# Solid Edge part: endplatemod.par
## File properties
Author: Deepak Maini
Template: NORMENG.PAR
Last saved by: CADCIM
Revision: 3
Application: Solid Edge
Accuracy: 0.99
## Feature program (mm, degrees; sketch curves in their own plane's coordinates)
sketch for "unnamed Protrusion 1" plane through (0, 0, 0) normal (0, 0, 1) x-axis (1, 0, 0)
  line (-50.8, 46.0858) -> (-50.8, -55.5142)
  line (-50.8, -55.5142) -> (50.8, -55.5142)
  line (50.8, -55.5142) -> (50.8, 46.0858)
  line (50.8, 46.0858) -> (-50.8, 46.0858)
extrude "unnamed Protrusion 1" add finite 12.7 along +normal
sketch for "Hole_1" plane through (0, -4.7142, 12.7) normal (0, 0, 1) x-axis (1, 0, 0)
  hole centre (-38.1, -38.1) bore radius 3.175
hole "Hole_1" diameter 6.35 through
sketch for "unnamed Hole 1" plane through (0, -4.7142, 12.7) normal (0, 0, 1) x-axis (1, 0, 0)
  hole centre (38.1, -38.1) bore radius 3.175
hole "unnamed Hole 1" through
sketch for "unnamed Hole 2" plane through (0, -4.7142, 12.7) normal (0, 0, 1) x-axis (1, 0, 0)
  hole centre (38.1, 38.1) bore radius 3.175
hole "unnamed Hole 2" through
sketch for "unnamed Hole 3" plane through (0, -4.7142, 12.7) normal (0, 0, 1) x-axis (1, 0, 0)
  hole centre (-38.1, 38.1) bore radius 3.175
  dimension (linear) = 38.1
hole "unnamed Hole 3" through
pattern "unnamed Pattern 1" of "Hole_1", "unnamed Hole 1", "unnamed Hole 2", "unnamed Hole 3"
sketch for "Hole_5" plane through (0, -4.7142, 12.7) normal (0, 0, 1) x-axis (1, 0, 0)
  hole centre (0, 0) bore radius 12.7
hole "Hole_5" diameter 25.4 through
sketch for "Hole_6" plane through (0, -4.7142, 12.7) normal (0, 0, 1) x-axis (1, 0, 0)
  hole centre (-20.6375, 0) bore radius 2.3812
  dimension (linear) = 20.6375
hole "Hole_6" diameter 4.7625 through
pattern "unnamed Pattern 2" of "Hole_6"
pattern "unnamed Pattern 3"
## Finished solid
Body 1: solid body, 15 faces, 30 edges, 8 vertices.
  Faces by surface: cylinder 9, plane 6
  Edges by curve: circle 18, line 12
Bounding box of the edges (mm): 101.600 x 101.600 x 12.700, from (-50.8, -55.5142, 0) to (50.8, 46.0858, 12.7).
Cylindrical faces by radius (mm): R2.3812 x4, R3.175 x4, R12.7 x1
Planar faces by outward normal: +x 1, +y 1, +z 1, -x 1, -y 1, -z 1
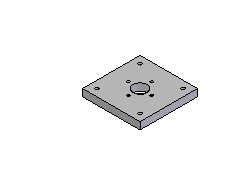
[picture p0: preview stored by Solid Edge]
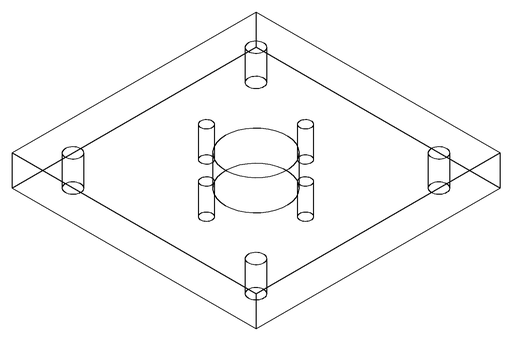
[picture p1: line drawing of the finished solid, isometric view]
